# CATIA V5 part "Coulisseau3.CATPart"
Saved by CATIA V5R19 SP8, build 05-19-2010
Part number: Coulisseau3
Bounding box of the stored display mesh (mm): x -7.5 to 3.5, y -15.777 to -8.223, z -13.494 to -2.506
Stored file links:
  C:\Users\ThinkMotion\Desktop\EU_thinkMotion\iao\IAO_MMS_Groupe3\pmayet\pmayet_avant_optimisation\pmayet_avant_optimisation\Coulisseau3.CATPart
  C:\Users\ThinkMotion\Desktop\EU_thinkMotion\iao\IAO_MMS_Groupe3\pmayet\pmayet_avant_optimisation\pmayet_avant_optimisation\pmayet.CATProduct
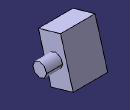
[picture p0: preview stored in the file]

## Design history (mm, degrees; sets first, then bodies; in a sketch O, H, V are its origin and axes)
Parameters
  Largeur_rainure_b = 5 mm
  Longueur_coulisseau = 10 mm
  Rayon_axe = 1.5 mm
  Longueur_axe = 3.5 mm
  Epaisseur_disque = 15 mm
Set1
  Plane1: linked copy from another document
  Line1: linked copy from another document
  Point1 "Point3": linked copy from another document
Body1 (main body)
  Sketch1 on Plane1, origin (0, 0, 0), H (0, 1, 0), V (0, 0, 1)
    line L1 (-15.7774, -3.8792) -> (-10.9698, -2.5056)
    line L2 (-10.9698, -2.5056) -> (-8.2226, -12.1208)
    line L3 (-8.2226, -12.1208) -> (-13.0302, -13.4944)
    line L4 (-13.0302, -13.4944) -> (-15.7774, -3.8792)
    reference projected line E1 (-12, -8) -> (-6.5056, -27.2305) from Line1
    reference projected line E2 (-12, -8) -> (-6.5056, -27.2305) from Line1
    reference projected line E3 (-12, -8) -> (-6.5056, -27.2305) from Line1
    reference projected line E4 (-12, -8) -> (-6.5056, -27.2305) from Line1
    reference projected point E5 (-12, -8) from Point1
    reference projected point E6 (-12, -8) from Point1
    distance L4 E1 = 2.5 {= Largeur_rainure_b /2}
    distance E3 L2 = 2.5 {= Largeur_rainure_b /2}
    distance E5 L1 = 5 {= Longueur_coulisseau /2}
    distance E6 L3 = 5 {= Longueur_coulisseau /2}
    parallelism: L4 E2, E4 L2
    perpendicularity: L3 L4, L1 L2
  Pad1: profile Sketch1, direction (-1, 0, 0), length 7.5 {= Epaisseur_disque /2}
  Sketch2 on Plane1, origin (0, 0, 0), H (0, 1, 0), V (0, 0, 1)
    circle A1 centre (-12, -8) radius 1.5
    point P1 (-12, -8)
    reference projected point E1 (-12, -8) from Point1
    distance P1 A1 = 1.5 {= Rayon_axe}
    coincidence: E1 P1
  Pad2: profile Sketch2, direction (1, 0, 0), length 3.5 {= Longueur_axe}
